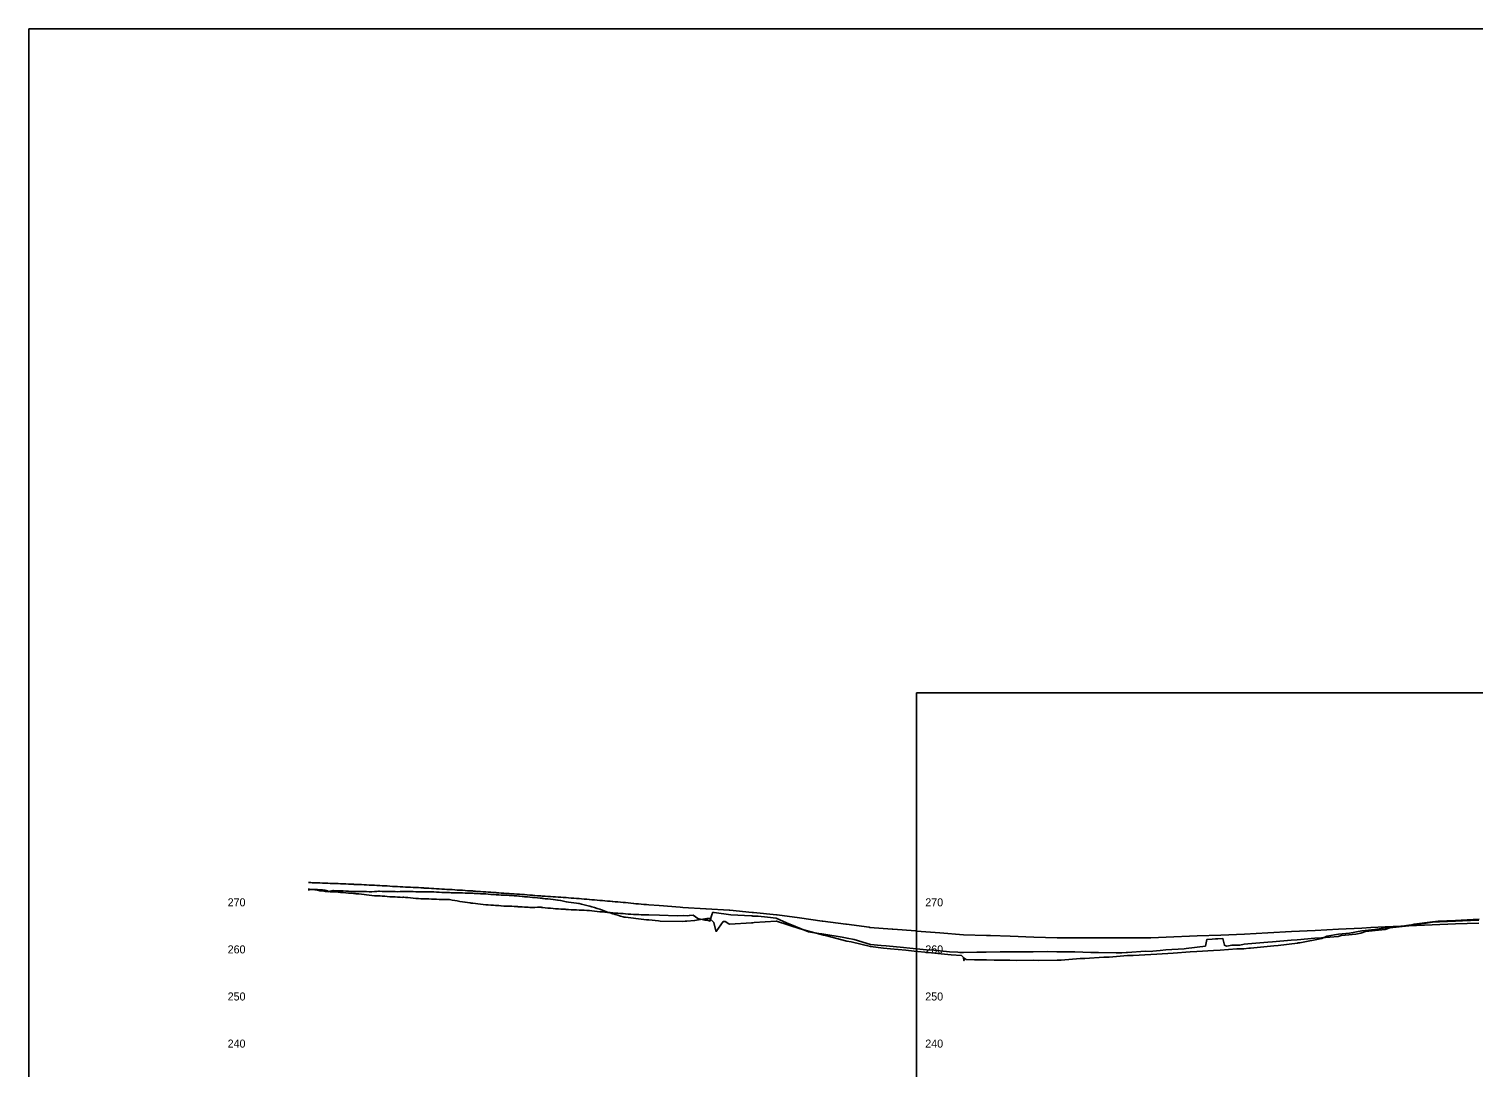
# Model space of a CAD drawing. Extents: x 2018315 to 2021915, y 966584 to 968784.
# Drawn here: x 2018315 to 2019848, y 967682 to 968784 of the extents above; entities that cross this region are included whole.
import ezdxf

# ---------------------------------------------------------------- set-up
doc = ezdxf.new("R2010")
doc.units = 0
for name, color, linetype in [('BR_EXIST_GROUND_LT', 7, 'Continuous'), ('BR_EXIST_GROUND_RT', 7, 'Continuous'), ('RD_DDB_ElevTX', 7, 'Continuous'), ('RD_DDB_Profile_EX', 7, 'Continuous'), ('RD_SHT_IplotShp', 7, 'Continuous'), ('RD_SHT_ShtClip', 7, 'Continuous')]:
    doc.layers.add(name, color=color, linetype=linetype)

msp = doc.modelspace()

# ---------------------------------------------------------------- linework, layer by layer
at = {"layer": 'BR_EXIST_GROUND_LT'}
msp.add_lwpolyline([(2018611, 967869.8), (2018612.6, 967870), (2018615, 967870.2), (2018615.4, 967870.1), (2018618.1, 967869.8), (2018620.9, 967869.4), (2018623.6, 967869), (2018626.4, 967868.7), (2018629.1, 967868.3), (2018631.9, 967868), (2018634.6, 967867.7), (2018635.5, 967867.6), (2018637.4, 967867.8), (2018638.6, 967867.9), (2018640.1, 967867.8), (2018642.9, 967867.5), (2018645.6, 967867.2), (2018648.4, 967866.9), (2018651.1, 967866.7), (2018653.9, 967866.4), (2018656.6, 967866.2), (2018659.4, 967866), (2018661, 967865.9), (2018662.1, 967865.8), (2018663.7, 967865.8), (2018664.9, 967865.6), (2018667.6, 967865.3), (2018670.4, 967864.9), (2018673.1, 967864.6), (2018675.9, 967864.3), (2018678.6, 967864), (2018681.4, 967863.7), (2018684.1, 967863.5), (2018685.5, 967863.4), (2018686.9, 967863.4), (2018687.5, 967863.4), (2018689.6, 967863.2), (2018692.4, 967863), (2018695.1, 967862.8), (2018697.9, 967862.6), (2018700.6, 967862.4), (2018703.4, 967862.3), (2018706.1, 967862.1), (2018708.9, 967862), (2018711.1, 967861.9), (2018711.6, 967862), (2018712.8, 967862.1), (2018714.4, 967861.9), (2018717.1, 967861.6), (2018719.9, 967861.3), (2018722.6, 967861.1), (2018725.4, 967860.8), (2018728.2, 967860.6), (2018730.9, 967860.4), (2018733.7, 967860.2), (2018734.8, 967860.2), (2018735.9, 967860.3), (2018736.4, 967860.3), (2018739.2, 967860.2), (2018741.9, 967860), (2018744.7, 967859.9), (2018747.4, 967859.9), (2018750.2, 967859.8), (2018752.9, 967859.8), (2018755.7, 967859.7), (2018758.4, 967859.8), (2018760.3, 967859.8), (2018761.2, 967859.6), (2018763.9, 967859.1), (2018766.7, 967858.6), (2018769.4, 967858.1), (2018772.2, 967857.6), (2018774.9, 967857.2), (2018777.7, 967856.7), (2018780.4, 967856.3), (2018783.2, 967856), (2018784.1, 967855.8), (2018784.4, 967855.8), (2018785.9, 967855.6), (2018788.7, 967855.3), (2018791.4, 967855), (2018794.2, 967854.7), (2018796.9, 967854.4), (2018799.7, 967854.1), (2018802.4, 967853.9), (2018805.2, 967853.7), (2018807.9, 967853.5), (2018810, 967853.4), (2018810.7, 967853.3), (2018813.4, 967853.1), (2018815.6, 967852.9), (2018816.2, 967852.8), (2018818.9, 967852.7), (2018821.7, 967852.6), (2018824.4, 967852.5), (2018827.2, 967852.4), (2018829.9, 967852.2), (2018832.7, 967852.1), (2018833.6, 967852.1), (2018833.9, 967852), (2018835.4, 967852), (2018838.2, 967851.8), (2018840.9, 967851.6), (2018843.7, 967851.4), (2018844.8, 967851.4), (2018846.4, 967851.3), (2018849.2, 967851.3), (2018851.9, 967851.3), (2018854.7, 967851.4), (2018857.4, 967851.4), (2018858.5, 967851.4), (2018859.2, 967851.3), (2018860.2, 967851.2), (2018862.9, 967850.9), (2018865.7, 967850.6), (2018868.4, 967850.3), (2018871.2, 967850), (2018873.9, 967849.8), (2018877, 967849.6), (2018879.4, 967849.4), (2018882.2, 967849.3), (2018884, 967849.2), (2018884.9, 967849.1), (2018887.7, 967849), (2018890.5, 967848.8), (2018893.2, 967848.6), (2018893.8, 967848.6), (2018896, 967848.5), (2018898.7, 967848.3), (2018901.5, 967848.2), (2018904.2, 967848.2), (2018907, 967848.1), (2018908.8, 967848), (2018910, 967847.8), (2018912.5, 967847.5), (2018915.2, 967847.3), (2018918, 967847), (2018920.7, 967846.7), (2018923.5, 967846.5), (2018926.2, 967846.2), (2018929, 967846), (2018931.7, 967845.8), (2018933.9, 967845.6), (2018934.5, 967845.5), (2018937.2, 967845.2), (2018940, 967845), (2018942.7, 967844.8), (2018945.5, 967844.6), (2018948.2, 967844.4), (2018951, 967844.2), (2018953.7, 967844), (2018956.5, 967843.8), (2018959.4, 967843.6), (2018962, 967843.6), (2018962.4, 967843.6), (2018964.7, 967843.5), (2018967.5, 967843.4), (2018970.2, 967843.3), (2018973, 967843.3), (2018984.2, 967842.9), (2019002.9, 967842.3), (2019009.3, 967842.6), (2019014.1, 967842.2), (2019016, 967842.8), (2019020, 967842.9), (2019024.8, 967839.4), (2019032.2, 967837.8), (2019035.3, 967837.7), (2019037.7, 967836.8), (2019040, 967844.4), (2019040.4, 967845.7), (2019042.1, 967845.7), (2019060, 967843.5), (2019081.7, 967842.3), (2019082.6, 967842.2), (2019083.4, 967842.1), (2019089, 967841.9), (2019099, 967840.8), (2019107.9, 967839.8), (2019119.1, 967835), (2019128.7, 967831), (2019142.4, 967825.2), (2019153.4, 967823.4), (2019156.7, 967823), (2019178.1, 967819.6), (2019179.9, 967819.3), (2019183.3, 967818.4), (2019190.9, 967817.1), (2019208.3, 967811.9), (2019219.4, 967810.7), (2019224.7, 967810.4), (2019243.4, 967808.5), (2019250.1, 967808), (2019267.8, 967806.3), (2019275.5, 967805.8), (2019292.2, 967804.1), (2019300.8, 967803.6), (2019303.1, 967803.3), (2019307, 967803.5), (2019321.2, 967803.8), (2019331.1, 967803.7), (2019345.9, 967804), (2019356.1, 967803.9), (2019370.9, 967804.2), (2019381.1, 967804), (2019395.9, 967804.4), (2019406.1, 967804.2), (2019417.8, 967803.9), (2019425.2, 967803.9), (2019442.2, 967803.5), (2019450.2, 967803.5), (2019469.1, 967802.9), (2019475.1, 967803), (2019479.8, 967803.3), (2019481.1, 967803.3), (2019499.9, 967804.7), (2019506.1, 967804.5), (2019507.9, 967804.8), (2019516, 967805.3), (2019521.8, 967806.2), (2019541.3, 967807.2), (2019543.6, 967807.6), (2019563.8, 967810.1), (2019565.4, 967817.3), (2019571.2, 967817.6), (2019574.7, 967817.9), (2019577.1, 967817.7), (2019582.4, 967818.1), (2019584.1, 967811), (2019586.2, 967810.1), (2019592.2, 967811.3), (2019600.5, 967811.2), (2019605.2, 967812.2), (2019608.8, 967812.5), (2019630, 967814.2), (2019635.2, 967814.7), (2019654.9, 967816.3), (2019661.3, 967816.8), (2019679.9, 967818.4), (2019687, 967819), (2019704.8, 967820.4), (2019708, 967821.4), (2019712.3, 967821.7), (2019723.6, 967822.7), (2019729, 967824), (2019729.9, 967824.3), (2019733.8, 967825.5), (2019754.8, 967827.8), (2019759.6, 967829.4), (2019779.7, 967831.7), (2019785.4, 967833.6), (2019804.9, 967836), (2019811.1, 967836.5), (2019829.4, 967837.3), (2019835.5, 967837.8), (2019854.4, 967838.7)], dxfattribs=at)
at = {"layer": 'BR_EXIST_GROUND_RT'}
msp.add_lwpolyline([(2018611, 967870.6), (2018611.5, 967870.6), (2018612.6, 967870.5), (2018615.4, 967870.4), (2018618.1, 967870.2), (2018620.9, 967870.1), (2018623.6, 967870), (2018626.4, 967869.8), (2018629.1, 967869.7), (2018631.9, 967869), (2018632.5, 967867.8), (2018634.6, 967868.4), (2018637.4, 967869.1), (2018637.8, 967869.2), (2018639.4, 967868.9), (2018640.1, 967868.9), (2018642.9, 967868.9), (2018645.6, 967868.9), (2018646.4, 967868.9), (2018648.4, 967868.8), (2018651.1, 967868.6), (2018653.9, 967868.5), (2018656.6, 967868.3), (2018659.4, 967868.2), (2018660.9, 967868.1), (2018661.5, 967868.1), (2018662.1, 967868.1), (2018664.9, 967868.1), (2018667.6, 967868), (2018670.4, 967868), (2018673.1, 967868), (2018675.9, 967867.9), (2018678.6, 967867.9), (2018681.4, 967868.1), (2018684.1, 967868.3), (2018685.9, 967868.4), (2018686.9, 967868.4), (2018689.6, 967868.3), (2018692.4, 967868.3), (2018695.1, 967868.2), (2018697.9, 967868.1), (2018700.6, 967868), (2018703.4, 967868), (2018706.1, 967867.9), (2018708.9, 967868), (2018710.4, 967868), (2018711.7, 967868), (2018712.1, 967868.1), (2018714.4, 967868), (2018717.1, 967868), (2018719.9, 967868), (2018722.6, 967868), (2018725.4, 967867.9), (2018728.2, 967867.9), (2018730.9, 967867.8), (2018732.1, 967867.8), (2018733.7, 967867.8), (2018736.6, 967867.9), (2018739.2, 967867.8), (2018741.9, 967867.7), (2018744.7, 967867.6), (2018747.4, 967867.5), (2018750.2, 967867.4), (2018752.9, 967867.2), (2018755.7, 967867.1), (2018758.7, 967866.9), (2018761.2, 967866.9), (2018763, 967866.8), (2018763.9, 967866.8), (2018766.7, 967866.8), (2018769.4, 967866.7), (2018772.2, 967866.7), (2018774.9, 967866.6), (2018777.7, 967866.5), (2018780.4, 967866.4), (2018783.2, 967866.3), (2018783.5, 967866.3), (2018785.9, 967866.2), (2018787.5, 967866.1), (2018788.7, 967866.1), (2018791.4, 967866), (2018794.2, 967865.8), (2018796.9, 967865.6), (2018799.7, 967865.5), (2018802.4, 967865.3), (2018805.2, 967865.1), (2018807.2, 967865), (2018807.9, 967864.9), (2018810.7, 967864.7), (2018811.9, 967864.6), (2018813.4, 967864.5), (2018816.2, 967864.4), (2018817.6, 967864.3), (2018818.9, 967864.2), (2018821.7, 967864.1), (2018824.4, 967863.9), (2018827.2, 967863.8), (2018829.9, 967863.6), (2018832.7, 967863.4), (2018834.9, 967863.3), (2018835.4, 967863.2), (2018838.2, 967862.9), (2018840.9, 967862.6), (2018843.9, 967862.3), (2018846.4, 967862.1), (2018849.2, 967861.9), (2018851.9, 967861.6), (2018854.7, 967861.4), (2018857.4, 967861.1), (2018859.3, 967860.9), (2018860.3, 967860.8), (2018861, 967860.7), (2018862.9, 967860.5), (2018865.7, 967860.2), (2018868.4, 967859.9), (2018871.2, 967859.6), (2018873.9, 967859.3), (2018876, 967859), (2018876.7, 967858.9), (2018879.4, 967858.4), (2018882.2, 967857.9), (2018884.9, 967857.3), (2018885.5, 967857.2), (2018887.7, 967856.9), (2018890.5, 967856.6), (2018893.2, 967856.2), (2018896, 967855.8), (2018898.1, 967855.5), (2018898.7, 967855.4), (2018901.5, 967854.7), (2018904.2, 967854), (2018907, 967853.4), (2018909.7, 967852.7), (2018910.1, 967852.6), (2018912.5, 967851.8), (2018915.2, 967851), (2018918, 967850.1), (2018920.7, 967849.2), (2018921.4, 967849), (2018923.5, 967848.3), (2018926.2, 967847.3), (2018929, 967846.3), (2018931.7, 967845.3), (2018933.6, 967844.7), (2018934.5, 967844.5), (2018935.3, 967844.3), (2018937.2, 967843.7), (2018940, 967842.9), (2018942.7, 967842.1), (2018945.5, 967841.3), (2018946.5, 967841), (2018948.2, 967840.7), (2018951, 967840.4), (2018953.7, 967840), (2018956.5, 967839.7), (2018959.2, 967839.4), (2018962, 967839.1), (2018964.7, 967838.7), (2018967.5, 967838.4), (2018970.2, 967838.2), (2018973, 967837.9), (2018983.2, 967837), (2018985, 967836.8), (2019008.1, 967836.2), (2019011.4, 967836.5), (2019013.2, 967836.6), (2019021.5, 967837.3), (2019034.5, 967839.6), (2019037.6, 967839.4), (2019038.2, 967838.8), (2019041.9, 967835.2), (2019043.9, 967826.3), (2019044.5, 967825.7), (2019051.8, 967836.3), (2019054, 967836.4), (2019057.9, 967833.7), (2019059, 967833.4), (2019081.9, 967834.9), (2019083.2, 967835), (2019084.6, 967835.2), (2019108.1, 967836.7), (2019108.4, 967836.6), (2019133.4, 967828.6), (2019137.3, 967827.3), (2019158.3, 967821.7), (2019160.6, 967821.3), (2019183.2, 967815.5), (2019187.6, 967814.8), (2019208.1, 967809.6), (2019222, 967808.1), (2019229.4, 967807.4), (2019245.7, 967805.7), (2019254.6, 967804.9), (2019269.7, 967803.3), (2019279.8, 967802.4), (2019293.8, 967801), (2019305, 967800), (2019307.1, 967797.9), (2019307.4, 967794.8), (2019307.6, 967795), (2019307.7, 967797.5), (2019309.9, 967795.8), (2019318.7, 967795.4), (2019331.3, 967795.5), (2019339.7, 967795.1), (2019356.3, 967795.2), (2019363.4, 967794.9), (2019381.4, 967795.1), (2019387, 967794.9), (2019406.4, 967795.2), (2019410.6, 967795.3), (2019431, 967796.9), (2019436, 967797), (2019456, 967798.4), (2019461.5, 967798.5), (2019481, 967800), (2019487.1, 967800), (2019506, 967801.4), (2019512.4, 967801.7), (2019529.6, 967802.8), (2019547.7, 967804), (2019554.6, 967804.4), (2019572.5, 967805.5), (2019579.6, 967805.9), (2019597.3, 967807.1), (2019604.6, 967807.4), (2019609.9, 967808), (2019611.6, 967808.1), (2019618.8, 967808.6), (2019636.6, 967810.6), (2019641.3, 967810.9), (2019661.6, 967813.4), (2019662.2, 967813.5), (2019664, 967813.7), (2019687.4, 967818.3), (2019692.8, 967820.7), (2019705.3, 967822.9), (2019716.8, 967824), (2019730, 967826.3), (2019743.9, 967827.7), (2019755, 967829.4), (2019770.2, 967831), (2019780, 967832.4), (2019796.1, 967834.1), (2019804.9, 967835.4), (2019812.3, 967835.9), (2019829.3, 967836.5), (2019836.7, 967837), (2019854.3, 967837.6)], dxfattribs=at)
at = {"layer": 'RD_DDB_Profile_EX'}
msp.add_lwpolyline([(2018611.6, 967877.6), (2018612.6, 967877.6), (2018614.1, 967877.6), (2018615.4, 967877.5), (2018618.1, 967877.4), (2018620.9, 967877.3), (2018623.6, 967877.2), (2018626.4, 967877.1), (2018629.1, 967877), (2018631.9, 967876.9), (2018634.6, 967876.8), (2018636.5, 967876.8), (2018637.4, 967876.7), (2018638.3, 967876.7), (2018640.1, 967876.6), (2018642.9, 967876.5), (2018645.6, 967876.4), (2018648.4, 967876.3), (2018651.1, 967876.1), (2018653.9, 967876), (2018656.6, 967875.9), (2018659.4, 967875.8), (2018660, 967875.7), (2018661.6, 967875.6), (2018662.1, 967875.6), (2018664.9, 967875.5), (2018667.6, 967875.4), (2018670.4, 967875.2), (2018673.1, 967875.1), (2018675.9, 967875), (2018678.6, 967874.8), (2018681.4, 967874.7), (2018684.1, 967874.6), (2018686.2, 967874.4), (2018687.2, 967874.4), (2018689.6, 967874.3), (2018692.4, 967874.1), (2018695.1, 967874), (2018697.9, 967873.8), (2018700.6, 967873.6), (2018703.4, 967873.5), (2018706.1, 967873.3), (2018708.9, 967873.1), (2018711.2, 967873), (2018711.6, 967873), (2018714.4, 967872.8), (2018717.1, 967872.7), (2018719.9, 967872.6), (2018722.6, 967872.4), (2018725.4, 967872.3), (2018728.2, 967872.2), (2018730.9, 967872), (2018733.7, 967871.9), (2018734.2, 967871.8), (2018735.7, 967871.7), (2018736.4, 967871.7), (2018737.3, 967871.6), (2018739.2, 967871.5), (2018741.9, 967871.4), (2018744.7, 967871.2), (2018747.4, 967871.1), (2018750.2, 967870.9), (2018752.9, 967870.7), (2018755.7, 967870.6), (2018758.4, 967870.4), (2018760.7, 967870.2), (2018761.2, 967870.2), (2018762.7, 967870.1), (2018763.9, 967870.1), (2018766.7, 967869.9), (2018769.4, 967869.7), (2018772.2, 967869.6), (2018774.9, 967869.4), (2018777.7, 967869.2), (2018780.4, 967869), (2018783.2, 967868.8), (2018785.9, 967868.7), (2018786.3, 967868.6), (2018788.1, 967868.5), (2018788.7, 967868.5), (2018791.4, 967868.3), (2018794.2, 967868.1), (2018796.9, 967867.9), (2018799.7, 967867.7), (2018802.4, 967867.5), (2018805.2, 967867.3), (2018807.9, 967867.1), (2018810.7, 967866.9), (2018811.2, 967866.8), (2018813.4, 967866.7), (2018816.2, 967866.5), (2018818.9, 967866.3), (2018821.7, 967866.1), (2018824.4, 967865.9), (2018827.2, 967865.7), (2018829.9, 967865.6), (2018832.7, 967865.4), (2018833.4, 967865.3), (2018834.6, 967865.2), (2018835.4, 967865.2), (2018838.2, 967865), (2018840.9, 967864.8), (2018843.7, 967864.6), (2018846.4, 967864.4), (2018849.2, 967864.1), (2018851.9, 967863.9), (2018854.7, 967863.7), (2018857.4, 967863.5), (2018858.3, 967863.4), (2018859.7, 967863.3), (2018860.2, 967863.3), (2018862.9, 967863.1), (2018865.7, 967862.9), (2018868.4, 967862.8), (2018871.2, 967862.6), (2018873.9, 967862.4), (2018876.7, 967862.2), (2018879.4, 967862), (2018881.9, 967861.8), (2018882.2, 967861.8), (2018884.4, 967861.6), (2018884.9, 967861.6), (2018887.7, 967861.4), (2018890.5, 967861.2), (2018893.2, 967861), (2018896, 967860.8), (2018898.7, 967860.6), (2018901.5, 967860.4), (2018904.2, 967860.1), (2018907, 967859.9), (2018909.4, 967859.7), (2018909.7, 967859.7), (2018912.5, 967859.4), (2018915.2, 967859.2), (2018918, 967859), (2018920.7, 967858.7), (2018923.5, 967858.5), (2018926.2, 967858.3), (2018929, 967858), (2018930.9, 967857.9), (2018931.7, 967857.8), (2018934, 967857.5), (2018934.5, 967857.5), (2018937.2, 967857.3), (2018940, 967857), (2018942.7, 967856.8), (2018945.5, 967856.5), (2018948.2, 967856.3), (2018951, 967856), (2018953.7, 967855.7), (2018956.5, 967855.5), (2018956.8, 967855.5), (2018959.2, 967855.2), (2018961, 967855), (2018962, 967855), (2018964.7, 967854.8), (2018967.5, 967854.5), (2018970.2, 967854.3), (2018973, 967854.1), (2018983.9, 967853.3), (2019006.2, 967851.5), (2019008.9, 967851.3), (2019033.4, 967849.8), (2019033.7, 967849.8), (2019058.1, 967848.3), (2019058.7, 967848.2), (2019082.7, 967845.8), (2019083.3, 967845.8), (2019083.9, 967845.7), (2019108.3, 967843.3), (2019109, 967843.2), (2019132.7, 967840), (2019157, 967836.8), (2019157.7, 967836.7), (2019181.9, 967833.5), (2019182.7, 967833.4), (2019206.9, 967830.1), (2019207.7, 967830), (2019231.4, 967828.2), (2019232, 967828.1), (2019256.5, 967826.2), (2019257, 967826.1), (2019281.7, 967824.2), (2019282, 967824.2), (2019307, 967822.2), (2019331.4, 967821.4), (2019335.5, 967821.3), (2019356.5, 967820.6), (2019381.6, 967819.8), (2019406.4, 967819.1), (2019406.7, 967819.1), (2019431.2, 967819), (2019456.1, 967819), (2019481.1, 967819), (2019506, 967819), (2019530.3, 967819.9), (2019547.1, 967820.6), (2019555.2, 967820.9), (2019580.3, 967821.9), (2019605.3, 967822.8), (2019630.3, 967824.2), (2019655.3, 967825.5), (2019680.3, 967826.8), (2019705.3, 967828.1), (2019729.9, 967829.3), (2019739.4, 967829.8), (2019754.8, 967830.5), (2019779.8, 967831.7), (2019804.8, 967832.9), (2019829.5, 967833.7), (2019854.2, 967834.6)], dxfattribs=at)
at = {"layer": 'RD_SHT_IplotShp'}
msp.add_lwpolyline([(2018314.5, 966584.2), (2021914.5, 966584.2), (2021914.5, 968784.2), (2018314.5, 968784.2)], close=True, dxfattribs=at)
at = {"layer": 'RD_SHT_ShtClip'}
msp.add_lwpolyline([(2019257.2, 968079.2), (2021057.2, 968079.2), (2021057.2, 966979.2), (2019257.2, 966979.2)], close=True, dxfattribs=at)

# ---------------------------------------------------------------- texts
at = {"layer": 'RD_DDB_ElevTX'}
for s, p in [('270', (2018525.6, 967852.4)), ('270', (2019266.4, 967852.4)), ('260', (2018525.6, 967802.4)), ('260', (2019266.4, 967802.4)), ('250', (2018525.6, 967752.4)), ('250', (2019266.4, 967752.4)), ('240', (2018525.6, 967702.4)), ('240', (2019266.4, 967702.4))]:
    msp.add_text(s, height=8.5, dxfattribs=at).set_placement(p)

doc.saveas('drawing.dxf')
